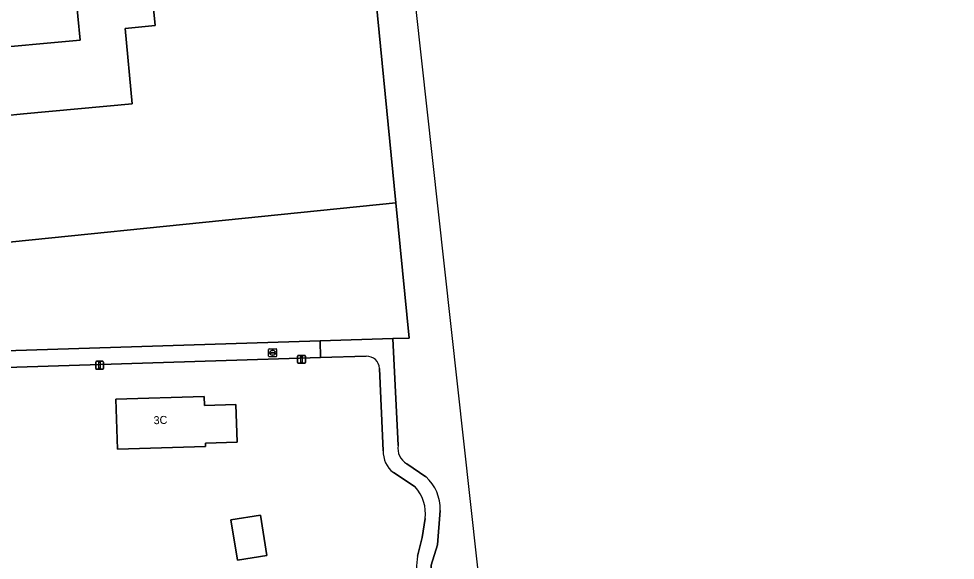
# Model space of a CAD drawing. Extents: x 162661 to 163484, y 380247 to 381230.
# Drawn here: x 163148.6 to 163265.6, y 380562.6 to 380630.3 of the extents above; entities that cross this region are included whole.
import ezdxf

# ---------------------------------------------------------------- set-up
doc = ezdxf.new("R2010")
doc.units = 0
for name, color, linetype in [('IMGEO_Erf', 7, 'Continuous'), ('IMGEO_Gemengd_bos', 7, 'Continuous'), ('IMGEO_Grasland_overig', 7, 'Continuous'), ('IMGEO_Groenvoorziening', 7, 'Continuous'), ('IMGEO_Hek', 7, 'Continuous'), ('IMGEO_Lichtmast', 7, 'Continuous'), ('IMGEO_Pand', 7, 'Continuous'), ('IMGEO_Pand_nummerreeks', 7, 'Continuous'), ('IMGEO_Rioolput', 7, 'Continuous'), ('IMGEO_Voetpad_open', 7, 'Continuous')]:
    doc.layers.add(name, color=color, linetype=linetype)

msp = doc.modelspace()

# ---------------------------------------------------------------- linework, layer by layer
at = {"layer": 'IMGEO_Erf'}
for points in [[(163121.17, 380651.71), (163126.07, 380600.19), (163195.7, 380607.28), (163192.68, 380638.45)], [(163192, 380588.11), (163186.32, 380587.94), (163127.36, 380586.09), (163131.15, 380546.24), (163131.39, 380542.91), (163135.59, 380543.62), (163135.47, 380544.26), (163137.26, 380544.54), (163145.33, 380545.79), (163147.15, 380546.1), (163147.52, 380543.89), (163150.23, 380544.28), (163154.23, 380544.96), (163190.01, 380550.74), (163198.03, 380552.22)], [(163194.15, 380576.29), (163193.68, 380586.57)], [(163198.14, 380571.77), (163195.41, 380573.55)], [(163198.44, 380563.11), (163198.99, 380565.44), (163199.37, 380567.8)]]:
    msp.add_lwpolyline(points, dxfattribs=at)
for points in [[(163156.25, 380627.65), (163155.69, 380633.7), (163160.67, 380634.16), (163165.14, 380634.58), (163165.62, 380629.46), (163161.89, 380629.11), (163162.76, 380619.67), (163149.18, 380618.41), (163144.21, 380617.95), (163143.42, 380626.47)], [(163160.92, 380576.48), (163160.88, 380577.74), (163160.72, 380582.74), (163171.76, 380583.08), (163171.79, 380581.95), (163175.72, 380582.07), (163175.87, 380577.37), (163171.91, 380577.24), (163171.92, 380576.83)], [(163175.11, 380567.64), (163178.78, 380568.23), (163179.59, 380563.18), (163175.93, 380562.59)]]:
    msp.add_lwpolyline(points, close=True, dxfattribs=at)
for centre, radius, start, end in [((163192.06, 380586.49), 1.62, 2.5918, 92.3472), ((163197.33, 380576.1), 3.19, 176.5855, 232.8982), ((163194.53, 380568.48), 4.88, 351.9437, 42.355), ((163206.41, 380561.7), 8.1, 169.9318, 193.0664)]:
    msp.add_arc(centre, radius, start, end, dxfattribs=at)
at = {"layer": 'IMGEO_Gemengd_bos'}
for points in [[(163382.18, 380751.8), (163381.37, 380750.92), (163360.63, 380736.31), (163338.62, 380722.02), (163315.49, 380708.25), (163313.61, 380707.45), (163296.99, 380698.55), (163283.61, 380692.06), (163243.79, 380678.45), (163216.2, 380669.24), (163189.78, 380667.06), (163191.08, 380656.97), (163192.68, 380638.45), (163195.7, 380607.28), (163197.37, 380590.38), (163195.33, 380590.32), (163195.99, 380576.94)], [(163268.69, 380368.54), (163218.02, 380452.54), (163201, 380606.54), (163194.78, 380662.88), (163218.22, 380669.19), (163320.57, 380704.35), (163382.69, 380751.14), (163382.18, 380751.8)], [(163197.08, 380574.66), (163199.48, 380573.04)], [(163201.25, 380568.83), (163200.92, 380564.51), (163200.14, 380561.97), (163200.17, 380559.39), (163201.66, 380552.04), (163205.91, 380526.29), (163205.95, 380524.36), (163205.39, 380513.18), (163205.44, 380509.62), (163206.28, 380500), (163207.03, 380495.24), (163208.27, 380489.24), (163210.2, 380475.87), (163211.49, 380457.68), (163212.75, 380451.99), (163215.2, 380445.27), (163216.89, 380441.84), (163240.42, 380399.93), (163252.66, 380378.82), (163260, 380368.84)]]:
    msp.add_lwpolyline(points, dxfattribs=at)
for centre, radius, start, end in [((163198.21, 380576.6), 2.24, 171.2248, 239.6102), ((163195.84, 380569.04), 5.41, 357.7832, 47.7553)]:
    msp.add_arc(centre, radius, start, end, dxfattribs=at)
at = {"layer": 'IMGEO_Grasland_overig'}
for points in [[(163195.99, 380576.94), (163195.33, 380590.32), (163186.25, 380590.03), (163186.32, 380587.94), (163192, 380588.11)], [(163193.68, 380586.57), (163194.15, 380576.29)], [(163195.41, 380573.55), (163198.14, 380571.77)], [(163199.48, 380573.04), (163197.08, 380574.66)], [(163260, 380368.84), (163252.66, 380378.82), (163240.42, 380399.93), (163216.89, 380441.84), (163215.2, 380445.27), (163212.75, 380451.99), (163211.49, 380457.68), (163210.2, 380475.87), (163208.27, 380489.24), (163207.03, 380495.24), (163206.28, 380500), (163205.44, 380509.62), (163205.39, 380513.18), (163205.95, 380524.36), (163205.91, 380526.29), (163201.66, 380552.04), (163200.17, 380559.39), (163200.14, 380561.97), (163200.92, 380564.51), (163201.25, 380568.83)], [(163199.37, 380567.8), (163198.99, 380565.44), (163198.44, 380563.11)]]:
    msp.add_lwpolyline(points, dxfattribs=at)
for centre, radius, start, end in [((163192.06, 380586.49), 1.62, 2.5918, 92.3472), ((163197.33, 380576.1), 3.19, 176.5855, 232.8982), ((163198.21, 380576.6), 2.24, 171.2248, 239.6102), ((163195.84, 380569.04), 5.41, 357.7832, 47.7553), ((163194.53, 380568.48), 4.88, 351.9437, 42.355), ((163206.41, 380561.7), 8.1, 169.9318, 193.0664)]:
    msp.add_arc(centre, radius, start, end, dxfattribs=at)
at = {"layer": 'IMGEO_Groenvoorziening'}
msp.add_lwpolyline([(163127.22, 380588.15), (163186.25, 380590.03), (163195.33, 380590.32), (163197.37, 380590.38), (163195.7, 380607.28), (163126.07, 380600.19)], close=True, dxfattribs=at)
at = {"layer": 'IMGEO_Hek'}
for points in [[(163191.08, 380656.97), (163192.68, 380638.45), (163195.7, 380607.28)], [(163195.7, 380607.28), (163126.07, 380600.19)]]:
    msp.add_lwpolyline(points, dxfattribs=at)
at = {"layer": 'IMGEO_Lichtmast'}
for p, q in [((163183.43, 380587.32), (163183.43, 380588.12)), ((163183.43, 380588.12), (163183.43, 380587.32)), ((163183.53, 380588.22), (163184.32, 380588.22)), ((163184.32, 380588.22), (163183.53, 380588.22)), ((163184.42, 380588.12), (163184.42, 380587.32)), ((163184.42, 380587.32), (163184.42, 380588.12)), ((163158.2, 380586.58), (163158.2, 380587.38)), ((163158.2, 380587.38), (163158.2, 380586.58)), ((163158.3, 380587.48), (163159.08, 380587.48)), ((163159.08, 380587.48), (163158.3, 380587.48)), ((163159.08, 380586.48), (163158.3, 380586.48)), ((163158.3, 380586.48), (163159.08, 380586.48)), ((163159.18, 380587.38), (163159.18, 380586.58)), ((163159.18, 380586.58), (163159.18, 380587.38)), ((163184.32, 380587.22), (163183.53, 380587.22)), ((163183.53, 380587.22), (163184.32, 380587.22))]:
    msp.add_line(p, q, dxfattribs=at)
for points in [[(163183.85, 380588.09), (163184, 380588.09), (163184, 380587.34), (163183.85, 380587.34), (163183.85, 380588.09)], [(163158.61, 380587.35), (163158.77, 380587.35), (163158.77, 380586.6), (163158.61, 380586.6), (163158.61, 380587.35)]]:
    msp.add_lwpolyline(points, dxfattribs=at)
for centre, start, end in [((163183.53, 380588.12), 90, 180), ((163183.53, 380588.12), 90, 180), ((163184.32, 380588.12), 0, 90), ((163184.32, 380588.12), 360, 90), ((163158.3, 380587.38), 90, 180), ((163158.3, 380587.38), 90, 180), ((163158.3, 380586.58), 180, 270), ((163158.3, 380586.58), 180, 270), ((163159.08, 380587.38), 0, 90), ((163159.08, 380587.38), 360, 90), ((163159.08, 380586.58), 270, 0), ((163159.08, 380586.58), 270, 0), ((163183.53, 380587.32), 180, 270), ((163183.53, 380587.32), 180, 270), ((163184.32, 380587.32), 270, 0), ((163184.32, 380587.32), 270, 0)]:
    msp.add_arc(centre, 0.1, start, end, dxfattribs=at)
at = {"layer": 'IMGEO_Pand'}
for points in [[(163160.67, 380634.16), (163155.69, 380633.7), (163156.25, 380627.65), (163143.42, 380626.47), (163144.21, 380617.95), (163149.18, 380618.41), (163162.76, 380619.67), (163161.89, 380629.11), (163165.62, 380629.46), (163165.14, 380634.58)], [(163171.79, 380581.95), (163171.76, 380583.08), (163160.72, 380582.74), (163160.88, 380577.74), (163160.92, 380576.48), (163171.92, 380576.83), (163171.91, 380577.24), (163175.87, 380577.37), (163175.72, 380582.07)], [(163175.11, 380567.64), (163175.93, 380562.59), (163179.59, 380563.18), (163178.78, 380568.23)]]:
    msp.add_lwpolyline(points, close=True, dxfattribs=at)
at = {"layer": 'IMGEO_Rioolput'}
for p, q in [((163179.82, 380588.11), (163179.82, 380588.97)), ((163179.89, 380589.04), (163180.75, 380589.04)), ((163180.31, 380588.82), (163180.33, 380588.82)), ((163180.82, 380588.97), (163180.82, 380588.11)), ((163180.75, 380588.04), (163179.89, 380588.04)), ((163180.08, 380588.53), (163180.08, 380588.55)), ((163180.12, 380588.58), (163180.52, 380588.58)), ((163180.52, 380588.5), (163180.12, 380588.5)), ((163180.33, 380588.26), (163180.3, 380588.26)), ((163180.56, 380588.55), (163180.56, 380588.53))]:
    msp.add_line(p, q, dxfattribs=at)
for points in [[(163179.82, 380588.11), (163179.82, 380588.97)], [(163179.89, 380589.04), (163180.75, 380589.04)], [(163180.82, 380588.97), (163180.82, 380588.11)], [(163180.75, 380588.04), (163179.89, 380588.04)]]:
    msp.add_lwpolyline(points, dxfattribs=at)
for centre, radius, start, end in [((163179.9, 380588.97), 0.0765, 91.552, 178.448), ((163179.9, 380588.97), 0.0765, 91.552, 178.448), ((163180.74, 380588.97), 0.0765, 1.552, 88.448), ((163180.74, 380588.97), 0.0765, 1.552, 88.448), ((163179.9, 380588.12), 0.0765, 181.552, 268.448), ((163179.9, 380588.12), 0.0765, 181.552, 268.448), ((163180.12, 380588.54), 0.0403, 85.8775, 175.7526), ((163180.11, 380588.53), 0.0366, 178.938, 274.7102), ((163180.52, 380588.55), 0.0386, 1.7309, 96.639), ((163180.52, 380588.54), 0.043, 264.8664, 352.4533), ((163180.74, 380588.12), 0.0765, 271.552, 358.448), ((163180.74, 380588.12), 0.0765, 271.552, 358.448)]:
    msp.add_arc(centre, radius, start, end, dxfattribs=at)
for centre, major_axis, ratio, start_param, end_param in [((163180.31, 380588.54), (-0.387, 0.002), 0.722429, 4.712389, 7.853982), ((163180.33, 380588.54), (-0.39, 0.002), 0.717154, 1.570796, 4.712389)]:
    msp.add_ellipse(centre, major_axis=major_axis, ratio=ratio, start_param=start_param, end_param=end_param, dxfattribs=at)
at = {"layer": 'IMGEO_Voetpad_open'}
msp.add_lwpolyline([(163127.36, 380586.09), (163186.32, 380587.94), (163186.25, 380590.03), (163127.22, 380588.15)], close=True, dxfattribs=at)

# ---------------------------------------------------------------- texts
at = {"layer": 'IMGEO_Pand_nummerreeks'}
msp.add_text('3C', height=1, rotation=1.8048, dxfattribs=at).set_placement((163165.46, 380579.6))

doc.saveas('drawing.dxf')
